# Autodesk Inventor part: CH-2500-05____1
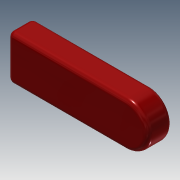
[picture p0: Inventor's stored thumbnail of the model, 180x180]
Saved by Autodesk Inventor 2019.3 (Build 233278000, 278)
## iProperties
Created: 2012-09
Part Number: CH-2500-05____1
Material: Ogólny
Document SubType Name: Modeling
Designer: CADENGINEERING4
Density: 1 g/cm^3
Appearance: Czerwona
Author: CADENGINEERING4
Revision Number: ÈÎºÎ
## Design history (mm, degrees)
feature "NONE"
node "Bryła1"
